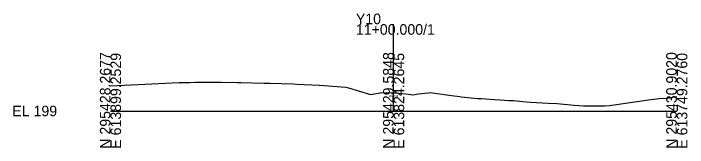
# Model space of a CAD drawing. Extents: x 517327 to 613901, y 114839 to 295511.
# Drawn here: x 517326.7 to 517505.2, y 116838.7 to 116874.2 of the extents above; entities that cross this region are included whole.
import ezdxf

# ---------------------------------------------------------------- set-up
doc = ezdxf.new("R2010")
doc.units = 0
for name, color, linetype in [('Old_Level_60', 7, 'Continuous'), ('Old_Level_63', 7, 'Continuous'), ('Old_Level_7', 7, 'Continuous')]:
    doc.layers.add(name, color=color, linetype=linetype)

msp = doc.modelspace()

# ---------------------------------------------------------------- linework, layer by layer
at = {"layer": 'Old_Level_63'}
for p, q in [((517427.36, 116848.36), (517427.36, 116871.39)), ((517352.36, 116848.36), (517427.36, 116848.36)), ((517427.36, 116848.36), (517502.36, 116848.36))]:
    msp.add_line(p, q, dxfattribs=at)
at = {"layer": 'Old_Level_7'}
for p, q in [((517352.36, 116855.01), (517370.54, 116855.91)), ((517370.54, 116855.91), (517373.39, 116855.88)), ((517373.39, 116855.88), (517374.91, 116856.02)), ((517374.91, 116856.02), (517376.88, 116856.04)), ((517376.88, 116856.04), (517378.88, 116856.04)), ((517378.88, 116856.04), (517379.68, 116856.02)), ((517379.68, 116856.02), (517381.67, 116856.03)), ((517381.67, 116856.03), (517385.99, 116855.9)), ((517385.99, 116855.9), (517386.39, 116855.9)), ((517386.39, 116855.9), (517386.93, 116855.9)), ((517386.93, 116855.9), (517393.02, 116855.76)), ((517393.02, 116855.76), (517393.62, 116855.74)), ((517393.62, 116855.74), (517394.63, 116855.7)), ((517394.63, 116855.7), (517400.63, 116855.58)), ((517400.63, 116855.58), (517401.76, 116855.51)), ((517401.76, 116855.51), (517407.63, 116855.23)), ((517407.63, 116855.23), (517409, 116855.15)), ((517409, 116855.15), (517414.68, 116854.66)), ((517414.68, 116854.66), (517415.4, 116854.48)), ((517415.4, 116854.48), (517421.23, 116852.74)), ((517421.23, 116852.74), (517423.77, 116853.18)), ((517423.77, 116853.18), (517424.11, 116853.24)), ((517424.11, 116853.24), (517427.04, 116853.16)), ((517427.04, 116853.16), (517427.38, 116853.16)), ((517427.38, 116853.16), (517427.71, 116853.14)), ((517427.71, 116853.14), (517430.58, 116852.93)), ((517430.58, 116852.93), (517431.18, 116852.85)), ((517431.18, 116852.85), (517432.44, 116852.67)), ((517432.44, 116852.67), (517433.98, 116852.9)), ((517433.98, 116852.9), (517436.53, 116853.2)), ((517436.53, 116853.2), (517437.17, 116853.28)), ((517437.17, 116853.28), (517437.62, 116853.22)), ((517437.62, 116853.22), (517442.7, 116852.49)), ((517442.7, 116852.49), (517444.91, 116852.2)), ((517444.91, 116852.2), (517445.21, 116852.16)), ((517445.21, 116852.16), (517449.63, 116851.72)), ((517449.63, 116851.72), (517450.75, 116851.64)), ((517450.75, 116851.64), (517452.85, 116851.5)), ((517452.85, 116851.5), (517456.64, 116851.27)), ((517456.64, 116851.27), (517457.9, 116851.19)), ((517457.9, 116851.19), (517459.13, 116851.13)), ((517459.13, 116851.13), (517461.62, 116850.87)), ((517484.53, 116849.83), (517495.52, 116851.42)), ((517495.52, 116851.42), (517497.06, 116851.63)), ((517497.06, 116851.63), (517497.58, 116851.66)), ((517497.58, 116851.66), (517499.79, 116851.74)), ((517499.79, 116851.74), (517501.94, 116852.09)), ((517501.94, 116852.09), (517502.36, 116852.11)), ((517461.62, 116850.87), (517463.64, 116850.68)), ((517463.64, 116850.68), (517468.33, 116850.45)), ((517468.33, 116850.45), (517470.64, 116850.34)), ((517470.64, 116850.34), (517475.21, 116849.87)), ((517475.21, 116849.87), (517477.64, 116849.76)), ((517477.64, 116849.76), (517481.92, 116849.72)), ((517481.92, 116849.72), (517483.19, 116849.75)), ((517483.19, 116849.75), (517484.53, 116849.83))]:
    msp.add_line(p, q, dxfattribs=at)

# ---------------------------------------------------------------- texts
at = {"layer": 'Old_Level_60'}
msp.add_text('203.793', height=0.5, dxfattribs=at).set_placement((517426.1, 116852.09))
at = {"layer": 'Old_Level_63'}
for s, p in [('Y10', (517417.36, 116871.39)), ('11+00.000/1', (517417.36, 116868.59)), ('EL 199', (517326.36, 116846.96))]:
    msp.add_text(s, height=2.8, dxfattribs=at).set_placement(p)
for s, p in [('N 295428.2677', (517352.36, 116838.36)), ('E 613899.2529', (517355.16, 116838.36)), ('N 295429.5848', (517427.36, 116838.36)), ('E 613824.2645', (517430.16, 116838.36)), ('N 295430.9020', (517502.36, 116838.36)), ('E 613749.2760', (517505.16, 116838.36))]:
    msp.add_text(s, height=2.8, rotation=90, dxfattribs=at).set_placement(p)

doc.saveas('drawing.dxf')
